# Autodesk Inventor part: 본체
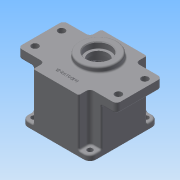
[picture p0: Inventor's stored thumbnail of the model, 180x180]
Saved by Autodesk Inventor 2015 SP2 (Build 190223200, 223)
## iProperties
Created: 2015-06
Part Number: 본체
Material: 일반
Document SubType Name: Modeling
Designer: AMC
Density: 1 g/cm^3
Appearance: 기본값
Author: AMC
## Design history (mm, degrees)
sketch "스케치1"
  geometry: L1 (-45, 45)-(45, 45); L2 (45, 45)-(45, -45); L3 (45, -45)-(-45, -45); L4 (-45, -45)-(-45, 45); 3 further points
  constraints: 8 end point, 2 midpoint, 2 parallel, 1 horizontal, 1 horizontal alignment, 1 perpendicular, 1 vertical alignment
  dimensions: "d6" = 90 distance of L2.end L3.end; "d7" = 90 distance of L3.end L1.start
extrude "돌출1" new body sketch "스케치1" distance "d8" = 7; taper "d9" = 0 deg
sketch "스케치11"
  geometry: L1 (-45, 45)-(-45, -45) reference; L2 (-45, 30)-(-45, -30); L3 (-45, -30)-(-30, -30); L4 (-30, -30)-(-30, -45); L5 (-45, -45)-(45, -45) reference; L6 (-30, -45)-(30, -45); L7 (30, -45)-(30, -30); L8 (30, -30)-(45, -30); L9 (45, -45)-(45, 45) reference; L10 (45, -30)-(45, 30); L11 (45, 30)-(30, 30); L12 (30, 30)-(30, 45); L13 (45, 45)-(-45, 45) reference; L14 (30, 45)-(-30, 45); L15 (-30, 45)-(-30, 30); L16 (-30, 30)-(-45, 30); 5 further points
  constraints: 24 end point, 13 point on line, 4 midpoint, 4 perpendicular, 3 horizontal alignment, 1 horizontal, 1 vertical alignment
  dimensions: "d47" = 60 distance between parallel lines of L3 L16; "d48" = 60 distance between parallel lines of L8 L11; "d49" = 60 distance between parallel lines of L12 L15
extrude "돌출9" join sketch "스케치11" distance "d50" = 51; taper "d51" = 0 deg
sketch "스케치12"
  geometry: L1 (-30, -45)-(-30, -30) reference; L2 (-30, -30)-(-45, -30) reference; L3 (-45, -30)-(-45, 30) reference; L4 (-45, 30)-(-30, 30) reference; L5 (-30, 30)-(-30, 45) reference; L6 (-30, 45)-(30, 45) reference; L7 (30, 45)-(30, 30) reference; L8 (30, 30)-(45, 30) reference; L9 (45, 30)-(45, -30) reference; L10 (45, -30)-(30, -30) reference; L11 (30, -30)-(30, -45) reference; L12 (30, -45)-(-30, -45) reference; L13 (-65, -30)-(65, -30); L14 (65, -30)-(65, 30); L15 (65, 30)-(-65, 30); L16 (-65, 30)-(-65, -30); L17 (-30, 45)-(30, 45); L18 (30, 45)-(30, -45); L19 (30, -45)-(-30, -45); L20 (-30, -45)-(-30, 45); 3 further points
  constraints: 16 end point, 4 parallel, 2 horizontal, 2 midpoint, 2 perpendicular, 1 horizontal alignment, 1 vertical alignment
  dimensions: "d52" = 130 distance of L13.start L13.end; "d53" = 60 distance of L15.end L13.start
  node "절단 모서리 투영5"
extrude "돌출10" join sketch "스케치12" distance "d54" = 12; taper "d55" = 0 deg
extrude "돌출11" join sketch "스케치12" distance "d56" = 12; taper "d57" = 0 deg
sketch "스케치13"
  geometry: C1 r 25 at (0, 11); 1 further point
  constraints: 1 centre point, 1 vertical alignment
  dimensions: "d58" = 50 diameter of C1; "d59" = 11 distance of point (0, 0) C1.centre
extrude "돌출12" join sketch "스케치13" distance "d60" = 7; taper "d61" = 0 deg
sketch "스케치14"
  geometry: L1 (36, 77)-(36, 70) reference; L2 (36, 70)-(45, 70) reference; L3 (45, 70)-(45, 0) reference; L4 (45, 0)-(-45, 0) reference; L5 (-45, 0)-(-45, 70) reference; L6 (-45, 70)-(-14, 70) reference; L7 (-14, 70)-(-14, 77) reference; L8 (-14, 77)-(36, 77) reference; L9 (36, 77)-(-14, 77) reference; L10 (11, 77)-(11, 54); L11 (11, 54)-(28.5, 54); L12 (28.5, 54)-(28.5, 64); L13 (28.5, 64)-(23.5, 64); L14 (23.5, 64)-(23.5, 69); L15 (23.5, 69)-(27, 69); L16 (27, 69)-(27, 77); L17 (27, 77)-(11, 77); 1 further point
  constraints: 16 end point, 6 perpendicular, 1 collinear, 1 midpoint, 1 point on line, 1 vertical
  dimensions: "d62" = 32 diameter of L16 L10; "d63" = 25 diameter of L14 L10; "d64" = 35 diameter of L12 L10; "d65" = 23 distance between parallel lines of L8 L11; "d66" = 8 distance between parallel lines of L17 L15; "d67" = 5 distance between parallel lines of L15 L13
revolve "회전2" sketch "스케치14" stored, may be unused: angle "d68" = 90 deg
sketch "스케치15"
  geometry: C1 r 40 at (0, 0); C2 r 39 at (0, 0); 1 further point
  constraints: 2 centre point, 2 coincident
  dimensions: "d69" = 80 diameter of C1; "d70" = 78 diameter of C2
extrude "돌출13" cut sketch "스케치15" distance "d71" = 61; taper "d72" = 0 deg
extrude "돌출14" cut sketch "스케치15" distance "d73" = 9; taper "d74" = 0 deg
sketch "스케치16"
  geometry: L1 (-65, 30)-(-30, 30) reference; L2 (-30, 30)-(-30, 45) reference; L3 (-30, 45)-(30, 45) reference; L4 (30, 45)-(30, 30) reference; L5 (30, 30)-(65, 30) reference; L6 (65, 30)-(65, -30) reference; L7 (65, -30)-(30, -30) reference; L8 (30, -45)-(-30, -45) reference; L9 (-30, -30)-(-65, -30) reference; L10 (-65, -30)-(-65, 30) reference; L11 (30, -30)-(30, -45) reference; L12 (-30, -45)-(-30, -30) reference; C1 r 20.5 at (0, 11); C2 r 39 at (0, 0) reference; C3 r 17.5 at (0, 11) reference; A1 r 14 centre (0, -20) between (-2.777, -6.278) and (2.777, -6.278); A2 r 17.5 centre (0, 11) between (2.777, -6.278) and (-2.777, -6.278); 1 further point
  constraints: 4 point on circle, 3 centre point, 2 vertical alignment, 1 coincident
  dimensions: "d77" = 11 distance of point (0, 0) C1.centre; "d78" = 20 distance of A1.centre point (0, 0); "d91" = 14 radius of A1; "d92" = 20.5 radius of C1; "d93" = 35 diameter of A2
extrude "돌출15" join sketch "스케치16" distance "d79" = 7; taper "d80" = 0 deg
sketch "스케치17"
  geometry: L1 (30, 30)-(45, 30) reference; L2 (45, 30)-(45, -30) reference; L3 (45, -30)-(30, -30) reference; L4 (30, -45)-(-30, -45) reference; L5 (-30, -30)-(-45, -30) reference; L6 (-45, -30)-(-45, 30) reference; L7 (-45, 30)-(-30, 30) reference; L8 (-30, 30)-(-30, 45) reference; L9 (-30, 45)-(30, 45) reference; L10 (30, 45)-(30, 30) reference; L11 (30, -30)-(30, -45) reference; L12 (-30, -45)-(-30, -30) reference; C1 r 17.5 at (0, 11) reference; C2 r 39 at (0, 0) reference; C3 r 11 at (0, -20); A1 r 20.5 centre (0, 11) between (7.402, -8.117) and (-7.402, -8.117) reference; A2 r 14 centre (0, -20) between (-7.402, -8.117) and (7.402, -8.117) reference; 2 further points
  constraints: 1 centre point, 1 coincident
  dimensions: "d90" = 22 diameter of C3
  node "절단 모서리 투영8"
extrude "돌출16" cut sketch "스케치17" distance "d95" = 7; taper "d96" = 0 deg
sketch "스케치18"
  geometry: L1 (-65, 50)-(-30, 50) reference; L2 (-30, 50)-(-30, 65) reference; L3 (-30, 65)-(30, 65) reference; L4 (30, 65)-(30, 50) reference; L5 (30, 50)-(65, 50) reference; L6 (65, 50)-(65, -10) reference; L7 (65, -10)-(30, -10) reference; L8 (30, -25)-(-30, -25) reference; L9 (-30, -10)-(-65, -10) reference; L10 (-65, -10)-(-65, 50) reference; L11 (30, -10)-(30, -25) reference; L12 (-30, -25)-(-30, -10) reference; C1 r 11 at (0, 0) reference; C2 r 39 at (0, 20) reference; C3 r 17.5 at (0, 31) reference; C4 r 9.5 at (0, 0); A1 r 20.5 centre (0, 31) between (7.402, 11.883) and (-7.402, 11.883) reference; A2 r 14 centre (0, 0) between (-7.402, 11.883) and (7.402, 11.883) reference; 1 further point
  constraints: 1 centre point, 1 coincident
  dimensions: "d97" = 19 diameter of C4
extrude "돌출17" cut sketch "스케치18" distance "d98" = 1; taper "d99" = 0 deg
sketch "스케치20"
  geometry: L1 (-65, 30)-(-30, 30) reference; L2 (-30, 30)-(-30, 45) reference; L3 (-30, 45)-(30, 45) reference; L4 (30, 45)-(30, 30) reference; L5 (30, 30)-(65, 30) reference; L6 (65, 30)-(65, -30) reference; L7 (65, -30)-(30, -30) reference; L8 (30, -45)-(-30, -45) reference; L9 (-30, -30)-(-65, -30) reference; L10 (-65, -30)-(-65, 30) reference; L11 (24.749, -24.749)-(0, 0); L12 (0, 0)-(29.346, 0); L13 (27.411, -21.763)-(30.401, -24.429); L14 (21.763, -27.411)-(24.789, -30.109); L15 (30, -30)-(30, -45) reference; L16 (-30, -45)-(-30, -30) reference; C1 r 9.5 at (0, -20) reference; C2 r 11 at (0, -20) reference; C3 r 17.5 at (0, 11) reference; A1 r 20.5 centre (0, 11) between (7.402, -8.117) and (-7.402, -8.117) reference; A2 r 14 centre (0, -20) between (-7.402, -8.117) and (7.402, -8.117) reference; A3 r 39 centre (0, 0) between (30.401, -24.429) and (24.789, -30.109) reference; A4 r 35 centre (0, 0) between (24.749, -24.749) and (27.411, -21.763); A5 r 4 centre (24.749, -24.749) between (27.411, -21.763) and (21.763, -27.411); 1 further point
  constraints: 8 end point, 7 point on circle, 2 centre point, 1 coincident, 1 horizontal, 1 parallel, 1 tangent
  dimensions: "d113" = 70 diameter of A4; "d114" = 8 diameter of A5; "d115" = 45 deg angle of L12 L11
extrude "돌출18" join sketch "스케치20" distance "d116" = 52; taper "d117" = 0 deg
hole "구멍2" diameter "d123" = 3.459; stored, may be unused: countersink angle "d127" = 90 deg, drill point angle "d129" = 118 deg; dims "d124" = 12, "d125" = 22, "d126" = 7, "d128" = 15, "d179" = 10, "d180" = 10
fillet "모깎기1" dims "d133" = 2
fillet "모깎기2" dims "d134" = 0.3
chamfer "모따기1" distance "d135" = 1; stored, may be unused: second distance "d136" = 2, angle "d137" = 45 deg
fillet "모깎기3" dims "d140" = 3
fillet "모깎기4" dims "d141" = 2
fillet "모깎기7" dims "d144" = 5
fillet "모깎기8" dims "d145" = 8
sketch "스케치22"
  geometry: L1 (30, 30)-(60, 30) reference; L2 (65, 25)-(65, -25) reference; L3 (-65, -25)-(-65, 25) reference; L4 (60, -30)-(30, -30) reference; L5 (30, -30)-(30, -45) reference; L6 (30, -45)-(-30, -45) reference; L7 (-30, -30)-(-60, -30) reference; L8 (-60, 30)-(-30, 30) reference; L9 (-30, 30)-(-30, 45) reference; L10 (-30, 45)-(30, 45) reference; L11 (30, 45)-(30, 30) reference; L12 (-30, -45)-(-30, -30) reference; L13 (-55, 17.5)-(-55, -17.5); L14 (55, 17.5)-(55, -17.5); C1 r 16 at (0, 11) reference; C2 r 27 at (0, 11) reference; C3 r 4.5 at (-55, 17.5); C4 r 4.5 at (-55, -17.5); C5 r 4.5 at (55, 17.5); C6 r 4.5 at (55, -17.5); A1 r 5 centre (60, 25) between (65, 25) and (60, 30) reference; A2 r 5 centre (60, -25) between (60, -30) and (65, -25) reference; A3 r 5 centre (-60, -25) between (-65, -25) and (-60, -30) reference; A4 r 5 centre (-60, 25) between (-60, 30) and (-65, 25) reference; 3 further points
  constraints: 4 centre point, 4 end point, 2 horizontal alignment, 2 midpoint, 2 vertical, 2 vertical alignment
  dimensions: "d160" = 9 diameter of C3; "d161" = 9 diameter of C4; "d162" = 35 distance of L13.end L13.start; "d163" = 10 distance from line of L13.start L3; "d164" = 9 diameter of C5; "d165" = 9 diameter of C6; "d166" = 35 distance of L14.end L14.start; "d167" = 10 distance from line of L14.start L2
  node "절단 모서리 투영13"
fillet "모깎기11" dims "d155" = 3.5
fillet "모깎기12" dims "d156" = 2
fillet "모깎기13" dims "d157" = 5
fillet "모깎기14" dims "d158" = 2
extrude "돌출19" cut sketch "스케치22" stored distance "d168" = 52; taper "d169" = 0 deg
sketch "스케치23"
  geometry: L1 (37, 43)-(32, 43) reference; L2 (43, 32)-(43, 37) reference; L3 (45, 28.536)-(45, -28.536) reference; L4 (43, -37)-(43, -32) reference; L5 (32, -43)-(37, -43) reference; L6 (28.536, -45)-(-28.536, -45) reference; L7 (-37, -43)-(-32, -43) reference; L8 (-43, -32)-(-43, -37) reference; L9 (-45, -28.536)-(-45, 28.536) reference; L10 (-43, 37)-(-43, 32) reference; L11 (-32, 43)-(-37, 43) reference; L12 (-28.536, 45)-(28.536, 45) reference; L13 (32, 35)-(32, 43) reference; L14 (43, 32)-(35, 32) reference; L15 (35, -32)-(43, -32) reference; L16 (32, -43)-(32, -35) reference; L17 (-32, -35)-(-32, -43) reference; L18 (-43, -32)-(-35, -32) reference; L19 (-35, 32)-(-43, 32) reference; L20 (-32, 43)-(-32, 35) reference; C1 r 40 at (0, 0) reference; C2 r 3.5 at (-37, 37); C3 r 3.5 at (-37, -37); C4 r 3.5 at (37, -37); C5 r 3.5 at (37, 37); A1 r 6 centre (37, 37) between (43, 37) and (37, 43) reference; A2 r 6 centre (37, -37) between (37, -43) and (43, -37) reference; A3 r 6 centre (-37, -37) between (-43, -37) and (-37, -43) reference; A4 r 6 centre (-37, 37) between (-37, 43) and (-43, 37) reference; A5 r 3 centre (35, 35) between (32, 35) and (35, 32) reference; A6 r 3 centre (35, -35) between (35, -32) and (32, -35) reference; A7 r 3 centre (-35, -35) between (-32, -35) and (-35, -32) reference; A8 r 3 centre (-35, 35) between (-35, 32) and (-32, 35) reference; 1 further point
  constraints: 4 centre point, 4 coincident, 8 other
  dimensions: "d170" = 7 diameter of C2; "d171" = 7 diameter of C3; "d172" = 7 diameter of C4; "d173" = 7 diameter of C5
extrude "돌출20" cut sketch "스케치23" stored distance "d174" = 52; taper "d175" = 0 deg
sketch "스케치24"
  geometry: L1 (-28, -45)-(28, -45) reference; 2 further points
  constraints: 1 vertical alignment, 1 other
  dimensions: "d176" = 15 distance from line of L1 point (0, -30)
feature "엠보싱1" sketch "스케치24" dims "d47" = 60, "d48" = 60, "d49" = 60, "d177" = 0.5, "d178" = 0
node "솔리드1"
pattern_circular "원형 패턴1" dims angle "d119" = 360 deg
pattern_circular "원형 패턴2" dims angle "d131" = 360 deg
node "절단 모서리 투영6"
node "절단 모서리 투영7"
node "절단 모서리 투영9"
node "절단 모서리 투영11"
node "절단 모서리 투영14"
